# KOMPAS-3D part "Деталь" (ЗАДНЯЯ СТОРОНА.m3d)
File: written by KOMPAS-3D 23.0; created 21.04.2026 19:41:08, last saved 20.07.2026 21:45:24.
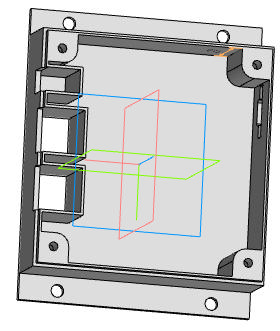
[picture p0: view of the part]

Document properties: Автор: D.LAB; Полное имя файла: C:\ЭЛЕКТРОНИКА\СХЕМЫ\Разное\ЦИФРОВОЙ ПРЕССОСТАТ ДЛЯ КОМПРЕССОРА\2.0 (питание от внешнего 12В)\Корпус\ЗАДНЯЯ СТОРОНА.m3d

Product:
- Part/product: Деталь
    Масса: 0.333812

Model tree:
1. ОСНОВАНИЕ
2. Элемент выдавливания:1
     Расстояние 1 = 2.15636
3. ОБРЕЗКА ОСНОВАНИЯ  (with: Элемент выдавливания:1)
4. Элемент выдавливания:2
     Расстояние 2 = 2.5
5. Эскиз:3  (with: Элемент выдавливания:2, Элемент выдавливания:1)
6. Элемент выдавливания:3
     Расстояние 2 = 1.5
7. Эскиз:4  (with: Элемент выдавливания:3)
8. Элемент выдавливания:4
     Расстояние 2 = 24
9. ВЫРЕЗ СЕРЕДИНЫ  (with: Элемент выдавливания:3)
10. Элемент выдавливания:5
     Расстояние 2 = 22
11. Эскиз:10  (with: Элемент выдавливания:1)
12. Элемент выдавливания:12
     Расстояние 2 = 4
13. ВЫРЕЗ ПОД БОРТ  (with: Элемент выдавливания:3, Элемент выдавливания:12)
14. Элемент выдавливания:13
     Расстояние 2 = 2.6
15. Эскиз:12  (with: Элемент выдавливания:1, Элемент выдавливания:4)
16. Элемент выдавливания:14
     Расстояние 2 = 15
17. КРЕПЕЖНАЯ ПОЛКА  (with: Элемент выдавливания:1)
18. Элемент выдавливания:15
     Расстояние 2 = 2
19. КРЕПЕЖНЫЕ ОТВ.  (with: Элемент выдавливания:15)
20. Элемент выдавливания:16
     Расстояние 2 = 2
21. Фаска:3  (with: Элемент выдавливания:14)
     Угол = 45; Длина 1 = 2; Длина 2 = 2
22. НАДПИСЬ НА ОБР. СТОРОНЕ  (with: Элемент выдавливания:1)
23. Элемент выдавливания:17
     Расстояние 2 = 1
24. ВЫРЕЗЫ ПОД КЛЕММНИКИ  (with: Элемент выдавливания:3, Элемент выдавливания:5)
25. Элемент выдавливания:18
     Расстояние 2 = 24
26. ВЫРЕЗЫ ПОД ПРОВОДА  (with: Элемент выдавливания:3, Элемент выдавливания:13, Элемент выдавливания:18, Элемент выдавливания:19)
     Расстояние 2 = 6
27. ВЫРЕЗ ПОД ПИТАНИЕ  (with: Элемент выдавливания:3, Элемент выдавливания:13, Элемент выдавливания:5)
28. Элемент выдавливания:24
     Расстояние 2 = 11.1
29. БОРТИКИ НА ВЫРЕЗЫ ПОД ПРОВОДА  (with: Элемент выдавливания:5, Элемент выдавливания:18, Элемент выдавливания:3, Элемент выдавливания:24, Элемент выдавливания:19)
30. Элемент выдавливания:25  (with: Элемент выдавливания:3)
     Расстояние 1 = 22
31. ВЫРЕЗ ПОД USB  (with: Элемент выдавливания:3, Элемент выдавливания:5)
32. Элемент выдавливания:26
     Расстояние 2 = 10
33. Скругление:2  (with: Элемент выдавливания:26)
     Радиус = 1
34. УГЛУБЛЕНИЕ ПОД ПЛАТУ АРДУИНО  (with: Элемент выдавливания:3, Скругление:2)
35. Элемент выдавливания:27
     Расстояние 2 = 1
36. Скругление:4  (with: Элемент выдавливания:27)
     Радиус = 1
37. Линейный размер:1  (with: Элемент выдавливания:3, Элемент выдавливания:5)
     Значение = 22

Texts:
  JUL.2026 v.2.0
